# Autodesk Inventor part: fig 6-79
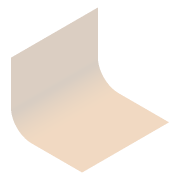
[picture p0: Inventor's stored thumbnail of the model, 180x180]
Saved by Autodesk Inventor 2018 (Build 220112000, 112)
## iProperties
Shininess: 64.0
Length Units: 11269
Angle Units: 11279
Time Units: 11290
Mass Units: 11283
Length Display Precision: 3
Angle Display Precision: 2
Compacted: True
Part Number: fig 6-79
Document SubType Name: Modeling
Created: 2003-10
Designer: Owner
Manufacturer: Standard
Standards Organization: Custom
Density: 1 g/cm^3
Material: Generic
Appearance: Default
Density: 0.0
Volumn: 0.0
Area: 0.0
PropertySet Name: Model Information
Control State: 0
Master: False
Checked Out: False
Author: Owner
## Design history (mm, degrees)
node "Sketch1"
sketch "Sketch2"
  geometry: L1 (22.777, 31.862)-(22.777, 0.2); L2 (7.777, -14.8)-(-29.161, -14.8); A1 r 15 centre (7.777, 0.2) between (7.777, -14.8) and (22.777, 0.2)
  constraints: 4 end point, 2 point on circle, 2 tangent, 1 centre point, 1 perpendicular, 1 vertical
  dimensions: "d23" = 15 radius of A1
extrude_surface "ExtrusionSrf1" sketch "Sketch2" dims "d24" = 63.5, "d25" = 0
body "Srf1"
